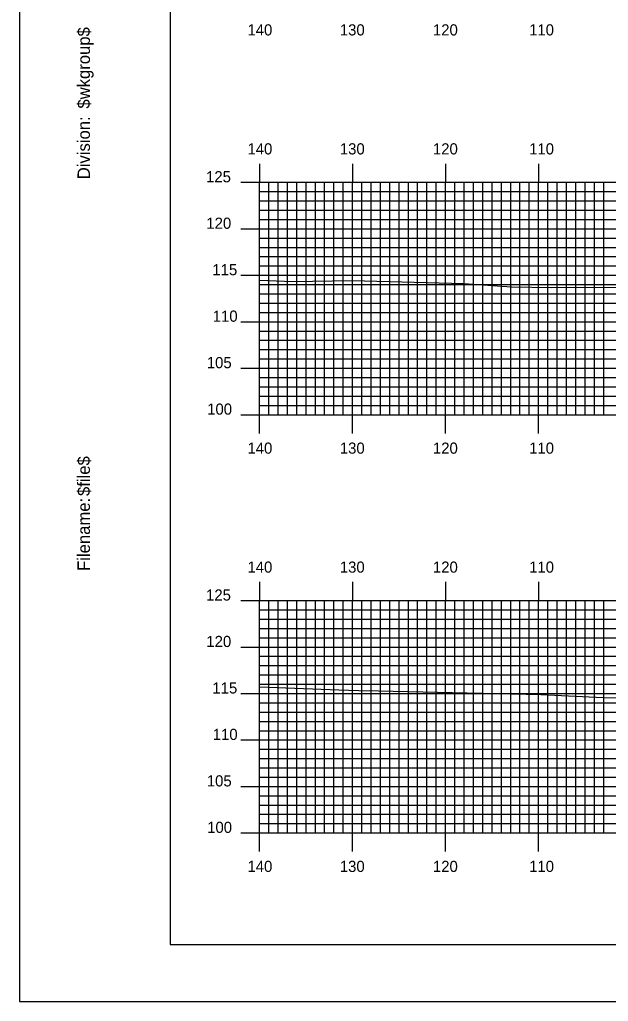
# Model space of a CAD drawing. Extents: x 1772809 to 1773153, y 442591 to 442811.
# Drawn here: x 1772809.3 to 1772872.6, y 442590.5 to 442696.2 of the extents above; entities that cross this region are included whole.
import ezdxf

# ---------------------------------------------------------------- set-up
doc = ezdxf.new("R2010")
doc.units = 0
for name, color, linetype in [('BORDER', 7, 'Continuous'), ('H_V ANNOTATION', 7, 'Continuous'), ('MAJOR', 7, 'Continuous'), ('MINOR', 7, 'Continuous'), ('PLOT BOUNDARY', 7, 'Continuous'), ('S_Roadway_Centerline', 7, 'Continuous')]:
    doc.layers.add(name, color=color, linetype=linetype)

msp = doc.modelspace()

# ---------------------------------------------------------------- linework, layer by layer
at = {"layer": 'BORDER'}
msp.add_lwpolyline([(1772825.52, 442596.67), (1773145.52, 442596.67), (1773145.52, 442806.67), (1772825.52, 442806.67)], close=True, dxfattribs=at)
at = {"layer": 'MAJOR'}
for p, q in [((1772835.12, 442680.67), (1772835.12, 442678.67)), ((1772845.12, 442680.67), (1772845.12, 442678.67)), ((1772855.12, 442680.67), (1772855.12, 442678.67)), ((1772865.12, 442680.67), (1772865.12, 442678.67)), ((1772833.12, 442678.67), (1772835.12, 442678.67)), ((1772835.12, 442678.67), (1773115.12, 442678.67)), ((1772835.12, 442653.67), (1772835.12, 442678.67)), ((1772835.12, 442653.67), (1772835.12, 442678.67)), ((1772835.12, 442678.67), (1773115.12, 442678.67)), ((1772845.12, 442653.67), (1772845.12, 442678.67)), ((1772855.12, 442653.67), (1772855.12, 442678.67)), ((1772865.12, 442653.67), (1772865.12, 442678.67)), ((1772833.12, 442673.67), (1772835.12, 442673.67)), ((1772835.12, 442673.67), (1773115.12, 442673.67)), ((1772833.12, 442668.67), (1772835.12, 442668.67)), ((1772835.12, 442668.67), (1773115.12, 442668.67)), ((1772833.12, 442663.67), (1772835.12, 442663.67)), ((1772835.12, 442663.67), (1773115.12, 442663.67)), ((1772833.12, 442658.67), (1772835.12, 442658.67)), ((1772835.12, 442658.67), (1773115.12, 442658.67)), ((1772833.12, 442653.67), (1772835.12, 442653.67)), ((1772835.12, 442653.67), (1773115.12, 442653.67)), ((1772835.12, 442653.67), (1773115.12, 442653.67)), ((1772835.12, 442651.66), (1772835.12, 442653.67)), ((1772845.12, 442651.66), (1772845.12, 442653.67)), ((1772855.12, 442651.66), (1772855.12, 442653.67)), ((1772865.12, 442651.66), (1772865.12, 442653.67)), ((1772835.12, 442635.67), (1772835.12, 442633.67)), ((1772845.12, 442635.67), (1772845.12, 442633.67)), ((1772855.12, 442635.67), (1772855.12, 442633.67)), ((1772865.12, 442635.67), (1772865.12, 442633.67)), ((1772833.12, 442633.67), (1772835.12, 442633.67)), ((1772835.12, 442633.67), (1773115.12, 442633.67)), ((1772835.12, 442608.67), (1772835.12, 442633.67)), ((1772835.12, 442608.67), (1772835.12, 442633.67)), ((1772835.12, 442633.67), (1773115.12, 442633.67)), ((1772845.12, 442608.67), (1772845.12, 442633.67)), ((1772855.12, 442608.67), (1772855.12, 442633.67)), ((1772865.12, 442608.67), (1772865.12, 442633.67)), ((1772833.12, 442628.67), (1772835.12, 442628.67)), ((1772835.12, 442628.67), (1773115.12, 442628.67)), ((1772833.12, 442623.67), (1772835.12, 442623.67)), ((1772835.12, 442623.67), (1773115.12, 442623.67)), ((1772833.12, 442618.67), (1772835.12, 442618.67)), ((1772835.12, 442618.67), (1773115.12, 442618.67)), ((1772833.12, 442613.67), (1772835.12, 442613.67)), ((1772835.12, 442613.67), (1773115.12, 442613.67)), ((1772833.12, 442608.67), (1772835.12, 442608.67)), ((1772835.12, 442608.67), (1773115.12, 442608.67)), ((1772835.12, 442608.67), (1773115.12, 442608.67)), ((1772835.12, 442606.66), (1772835.12, 442608.67)), ((1772845.12, 442606.66), (1772845.12, 442608.67)), ((1772855.12, 442606.66), (1772855.12, 442608.67)), ((1772865.12, 442606.66), (1772865.12, 442608.67))]:
    msp.add_line(p, q, dxfattribs=at)
at = {"layer": 'MINOR'}
for p, q in [((1772836.12, 442653.67), (1772836.12, 442678.67)), ((1772837.12, 442653.67), (1772837.12, 442678.67)), ((1772838.12, 442653.67), (1772838.12, 442678.67)), ((1772839.12, 442653.67), (1772839.12, 442678.67)), ((1772840.12, 442653.67), (1772840.12, 442678.67)), ((1772841.12, 442653.67), (1772841.12, 442678.67)), ((1772842.12, 442653.67), (1772842.12, 442678.67)), ((1772843.12, 442653.67), (1772843.12, 442678.67)), ((1772844.12, 442653.67), (1772844.12, 442678.67)), ((1772846.12, 442653.67), (1772846.12, 442678.67)), ((1772847.12, 442653.67), (1772847.12, 442678.67)), ((1772848.12, 442653.67), (1772848.12, 442678.67)), ((1772849.12, 442653.67), (1772849.12, 442678.67)), ((1772850.12, 442653.67), (1772850.12, 442678.67)), ((1772851.12, 442653.67), (1772851.12, 442678.67)), ((1772852.12, 442653.67), (1772852.12, 442678.67)), ((1772853.12, 442653.67), (1772853.12, 442678.67)), ((1772854.12, 442653.67), (1772854.12, 442678.67)), ((1772856.12, 442653.67), (1772856.12, 442678.67)), ((1772857.12, 442653.67), (1772857.12, 442678.67)), ((1772858.12, 442653.67), (1772858.12, 442678.67)), ((1772859.12, 442653.67), (1772859.12, 442678.67)), ((1772860.12, 442653.67), (1772860.12, 442678.67)), ((1772861.12, 442653.67), (1772861.12, 442678.67)), ((1772862.12, 442653.67), (1772862.12, 442678.67)), ((1772863.12, 442653.67), (1772863.12, 442678.67)), ((1772864.12, 442653.67), (1772864.12, 442678.67)), ((1772866.12, 442653.67), (1772866.12, 442678.67)), ((1772867.12, 442653.67), (1772867.12, 442678.67)), ((1772868.12, 442653.67), (1772868.12, 442678.67)), ((1772869.12, 442653.67), (1772869.12, 442678.67)), ((1772870.12, 442653.67), (1772870.12, 442678.67)), ((1772871.12, 442653.67), (1772871.12, 442678.67)), ((1772872.12, 442653.67), (1772872.12, 442678.67)), ((1772835.12, 442677.67), (1773115.12, 442677.67)), ((1772835.12, 442677.67), (1772837.12, 442677.67)), ((1772835.12, 442676.67), (1773115.12, 442676.67)), ((1772835.12, 442676.67), (1772837.12, 442676.67)), ((1772835.12, 442675.67), (1773115.12, 442675.67)), ((1772835.12, 442675.67), (1772837.12, 442675.67)), ((1772835.12, 442674.67), (1773115.12, 442674.67)), ((1772835.12, 442674.67), (1772837.12, 442674.67)), ((1772835.12, 442672.67), (1773115.12, 442672.67)), ((1772835.12, 442672.67), (1772837.12, 442672.67)), ((1772835.12, 442671.67), (1773115.12, 442671.67)), ((1772835.12, 442671.67), (1772837.12, 442671.67)), ((1772835.12, 442670.67), (1773115.12, 442670.67)), ((1772835.12, 442670.67), (1772837.12, 442670.67)), ((1772835.12, 442669.67), (1773115.12, 442669.67)), ((1772835.12, 442669.67), (1772837.12, 442669.67)), ((1772835.12, 442667.67), (1773115.12, 442667.67)), ((1772835.12, 442667.67), (1772837.12, 442667.67)), ((1772835.12, 442666.67), (1773115.12, 442666.67)), ((1772835.12, 442666.67), (1772837.12, 442666.67)), ((1772835.12, 442665.67), (1773115.12, 442665.67)), ((1772835.12, 442665.67), (1772837.12, 442665.67)), ((1772835.12, 442664.67), (1773115.12, 442664.67)), ((1772835.12, 442664.67), (1772837.12, 442664.67)), ((1772835.12, 442662.67), (1773115.12, 442662.67)), ((1772835.12, 442662.67), (1772837.12, 442662.67)), ((1772835.12, 442661.67), (1773115.12, 442661.67)), ((1772835.12, 442661.67), (1772837.12, 442661.67)), ((1772835.12, 442660.67), (1773115.12, 442660.67)), ((1772835.12, 442660.67), (1772837.12, 442660.67)), ((1772835.12, 442659.67), (1773115.12, 442659.67)), ((1772835.12, 442659.67), (1772837.12, 442659.67)), ((1772835.12, 442657.67), (1773115.12, 442657.67)), ((1772835.12, 442657.67), (1772837.12, 442657.67)), ((1772835.12, 442656.67), (1773115.12, 442656.67)), ((1772835.12, 442656.67), (1772837.12, 442656.67)), ((1772835.12, 442655.67), (1773115.12, 442655.67)), ((1772835.12, 442655.67), (1772837.12, 442655.67)), ((1772835.12, 442654.67), (1773115.12, 442654.67)), ((1772835.12, 442654.67), (1772837.12, 442654.67)), ((1772836.12, 442608.67), (1772836.12, 442633.67)), ((1772837.12, 442608.67), (1772837.12, 442633.67)), ((1772838.12, 442608.67), (1772838.12, 442633.67)), ((1772839.12, 442608.67), (1772839.12, 442633.67)), ((1772840.12, 442608.67), (1772840.12, 442633.67)), ((1772841.12, 442608.67), (1772841.12, 442633.67)), ((1772842.12, 442608.67), (1772842.12, 442633.67)), ((1772843.12, 442608.67), (1772843.12, 442633.67)), ((1772844.12, 442608.67), (1772844.12, 442633.67)), ((1772846.12, 442608.67), (1772846.12, 442633.67)), ((1772847.12, 442608.67), (1772847.12, 442633.67)), ((1772848.12, 442608.67), (1772848.12, 442633.67)), ((1772849.12, 442608.67), (1772849.12, 442633.67)), ((1772850.12, 442608.67), (1772850.12, 442633.67)), ((1772851.12, 442608.67), (1772851.12, 442633.67)), ((1772852.12, 442608.67), (1772852.12, 442633.67)), ((1772853.12, 442608.67), (1772853.12, 442633.67)), ((1772854.12, 442608.67), (1772854.12, 442633.67)), ((1772856.12, 442608.67), (1772856.12, 442633.67)), ((1772857.12, 442608.67), (1772857.12, 442633.67)), ((1772858.12, 442608.67), (1772858.12, 442633.67)), ((1772859.12, 442608.67), (1772859.12, 442633.67)), ((1772860.12, 442608.67), (1772860.12, 442633.67)), ((1772861.12, 442608.67), (1772861.12, 442633.67)), ((1772862.12, 442608.67), (1772862.12, 442633.67)), ((1772863.12, 442608.67), (1772863.12, 442633.67)), ((1772864.12, 442608.67), (1772864.12, 442633.67)), ((1772866.12, 442608.67), (1772866.12, 442633.67)), ((1772867.12, 442608.67), (1772867.12, 442633.67)), ((1772868.12, 442608.67), (1772868.12, 442633.67)), ((1772869.12, 442608.67), (1772869.12, 442633.67)), ((1772870.12, 442608.67), (1772870.12, 442633.67)), ((1772871.12, 442608.67), (1772871.12, 442633.67)), ((1772872.12, 442608.67), (1772872.12, 442633.67)), ((1772835.12, 442632.67), (1773115.12, 442632.67)), ((1772835.12, 442632.67), (1772837.12, 442632.67)), ((1772835.12, 442631.67), (1773115.12, 442631.67)), ((1772835.12, 442631.67), (1772837.12, 442631.67)), ((1772835.12, 442630.67), (1773115.12, 442630.67)), ((1772835.12, 442630.67), (1772837.12, 442630.67)), ((1772835.12, 442629.67), (1773115.12, 442629.67)), ((1772835.12, 442629.67), (1772837.12, 442629.67)), ((1772835.12, 442627.67), (1773115.12, 442627.67)), ((1772835.12, 442627.67), (1772837.12, 442627.67)), ((1772835.12, 442626.67), (1773115.12, 442626.67)), ((1772835.12, 442626.67), (1772837.12, 442626.67)), ((1772835.12, 442625.67), (1773115.12, 442625.67)), ((1772835.12, 442625.67), (1772837.12, 442625.67)), ((1772835.12, 442624.67), (1773115.12, 442624.67)), ((1772835.12, 442624.67), (1772837.12, 442624.67)), ((1772835.12, 442622.67), (1773115.12, 442622.67)), ((1772835.12, 442622.67), (1772837.12, 442622.67)), ((1772835.12, 442621.67), (1773115.12, 442621.67)), ((1772835.12, 442621.67), (1772837.12, 442621.67)), ((1772835.12, 442620.67), (1773115.12, 442620.67)), ((1772835.12, 442620.67), (1772837.12, 442620.67)), ((1772835.12, 442619.67), (1773115.12, 442619.67)), ((1772835.12, 442619.67), (1772837.12, 442619.67)), ((1772835.12, 442617.67), (1773115.12, 442617.67)), ((1772835.12, 442617.67), (1772837.12, 442617.67)), ((1772835.12, 442616.67), (1773115.12, 442616.67)), ((1772835.12, 442616.67), (1772837.12, 442616.67)), ((1772835.12, 442615.67), (1773115.12, 442615.67)), ((1772835.12, 442615.67), (1772837.12, 442615.67)), ((1772835.12, 442614.67), (1773115.12, 442614.67)), ((1772835.12, 442614.67), (1772837.12, 442614.67)), ((1772835.12, 442612.67), (1773115.12, 442612.67)), ((1772835.12, 442612.67), (1772837.12, 442612.67)), ((1772835.12, 442611.67), (1773115.12, 442611.67)), ((1772835.12, 442611.67), (1772837.12, 442611.67)), ((1772835.12, 442610.67), (1773115.12, 442610.67)), ((1772835.12, 442610.67), (1772837.12, 442610.67)), ((1772835.12, 442609.67), (1773115.12, 442609.67)), ((1772835.12, 442609.67), (1772837.12, 442609.67))]:
    msp.add_line(p, q, dxfattribs=at)
at = {"layer": 'PLOT BOUNDARY'}
msp.add_lwpolyline([(1772809.33, 442590.55), (1773149.33, 442590.55), (1773149.33, 442810.55), (1772809.33, 442810.55)], close=True, dxfattribs=at)
at = {"layer": 'S_Roadway_Centerline'}
for points in [[(1772835.12, 442668.15), (1772838.69, 442667.99), (1772845.07, 442668.09), (1772857.08, 442667.77), (1772862.21, 442667.41), (1772866.54, 442667.34), (1772882.78, 442667.38), (1772884.99, 442667.38), (1772887.09, 442667.3), (1772901.27, 442666.64), (1772908.01, 442666.48), (1772920.06, 442666.22), (1772929.24, 442666.01), (1772935.48, 442665.74), (1772951.58, 442665.24)], [(1772835.12, 442624.38), (1772843.63, 442624.06), (1772845.8, 442623.99), (1772847.9, 442623.96), (1772865.35, 442623.55), (1772872.07, 442623.24), (1772885.25, 442622.96), (1772897.99, 442622.8), (1772902.98, 442622.54), (1772923.61, 442622.34), (1772925.62, 442622.3), (1772927.49, 442622.2), (1772938.72, 442621.3)]]:
    msp.add_lwpolyline(points, dxfattribs=at)

# ---------------------------------------------------------------- texts
at = {"layer": 'BORDER'}
for s, p in [('$wkgroup$', (1772816.89, 442686.6)), ('Division:', (1772816.89, 442679)), ('$file$', (1772816.89, 442644.92)), ('Filename:', (1772816.89, 442636.86))]:
    msp.add_text(s, height=1.339, rotation=90, dxfattribs=at).set_placement(p)
at = {"layer": 'H_V ANNOTATION'}
for s, p in [('140', (1772833.82, 442694.47)), ('130', (1772843.75, 442694.47)), ('120', (1772853.76, 442694.47)), ('110', (1772864.1, 442694.47)), ('140', (1772833.82, 442681.67)), ('130', (1772843.75, 442681.67)), ('120', (1772853.76, 442681.67)), ('110', (1772864.1, 442681.67)), ('125', (1772829.37, 442678.67)), ('120', (1772829.4, 442673.67)), ('115', (1772830.05, 442668.67)), ('110', (1772830.09, 442663.67)), ('105', (1772829.45, 442658.67)), ('100', (1772829.49, 442653.67)), ('140', (1772833.82, 442649.47)), ('130', (1772843.75, 442649.47)), ('120', (1772853.76, 442649.47)), ('110', (1772864.1, 442649.47)), ('140', (1772833.82, 442636.67)), ('130', (1772843.75, 442636.67)), ('120', (1772853.76, 442636.67)), ('110', (1772864.1, 442636.67)), ('125', (1772829.37, 442633.67)), ('120', (1772829.4, 442628.67)), ('115', (1772830.05, 442623.67)), ('110', (1772830.09, 442618.67)), ('105', (1772829.45, 442613.67)), ('100', (1772829.49, 442608.67)), ('140', (1772833.82, 442604.47)), ('130', (1772843.75, 442604.47)), ('120', (1772853.76, 442604.47)), ('110', (1772864.1, 442604.47))]:
    msp.add_text(s, height=1.2, dxfattribs=at).set_placement(p)
at = {"layer": 'MAJOR'}
for p in [(1772835.11, 442653.67), (1772835.11, 442608.67)]:
    msp.add_text('-', height=0.012, dxfattribs=at).set_placement(p)

doc.saveas('drawing.dxf')
